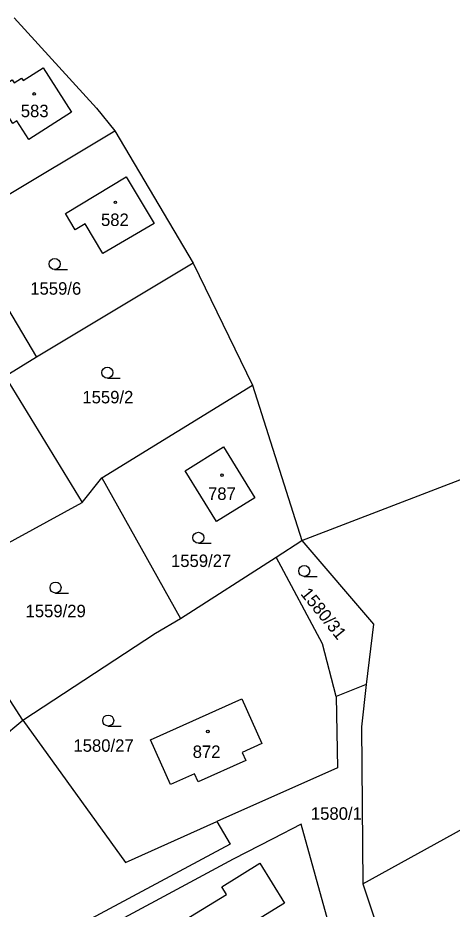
# Model space of a CAD drawing. Extents: x -725728 to -720881, y -1068679 to -1063504.
# Drawn here: x -723628.2 to -723569, y -1066824.1 to -1066702.5 of the extents above; entities that cross this region are included whole.
import ezdxf

# ---------------------------------------------------------------- set-up
doc = ezdxf.new("R2010")
doc.units = 0
for name, color, linetype in [('Hranice parcel', 7, 'Continuous'), ('Parcelní čísla', 7, 'Continuous'), ('Značky budov', 7, 'Continuous'), ('Značky kultur', 7, 'Continuous')]:
    doc.layers.add(name, color=color, linetype=linetype)

# ---------------------------------------------------------------- blocks, each defined once
blk = doc.blocks.new('4.02_3')
at = {"layer": 'Značky budov'}
blk.add_circle((-0.001, 0), 0.0175, dxfattribs=at)
blk = doc.blocks.new('4.02_4')
at = {"layer": 'Značky budov'}
blk.add_circle((-0.001, 0), 0.0175, dxfattribs=at)
blk = doc.blocks.new('3.04_3')
at = {"layer": 'Značky kultur'}
blk.add_line((0.001, 0), (0.176, 0), dxfattribs=at)
blk.add_circle((0.001, 0.075), 0.075, dxfattribs=at)
blk = doc.blocks.new('3.04_2')
at = {"layer": 'Značky kultur'}
blk.add_line((0.001, 0), (0.176, 0), dxfattribs=at)
blk.add_circle((0.001, 0.075), 0.075, dxfattribs=at)

msp = doc.modelspace()

# ---------------------------------------------------------------- linework, layer by layer
at = {"layer": 'Hranice parcel'}
for p, q in [((-723636.48, -1066730.78), (-723614.98, -1066717.9)), ((-723614.98, -1066717.9), (-723604.29, -1066735.93)), ((-723636.48, -1066730.78), (-723625.65, -1066748.76)), ((-723604.29, -1066735.93), (-723625.65, -1066748.76)), ((-723604.29, -1066735.93), (-723596.21, -1066752.59)), ((-723625.65, -1066748.76), (-723629.93, -1066751.39)), ((-723629.93, -1066751.39), (-723619.44, -1066768.6)), ((-723616.74, -1066765.23), (-723596.21, -1066752.59)), ((-723596.21, -1066752.59), (-723589.47, -1066773.79)), ((-723589.47, -1066773.79), (-723540.58, -1066754.95)), ((-723619.44, -1066768.6), (-723616.74, -1066765.23)), ((-723616.74, -1066765.23), (-723606.03, -1066784.4)), ((-723639.64, -1066779.61), (-723619.44, -1066768.6)), ((-723592.97, -1066776.06), (-723589.47, -1066773.79)), ((-723606.03, -1066784.4), (-723592.97, -1066776.06)), ((-723627.51, -1066798.3), (-723639.64, -1066779.61)), ((-723581.16, -1066820.61), (-723518.57, -1066786.09)), ((-723580.67, -1066793.4), (-723584.79, -1066795.05)), ((-723630.58, -1066800.81), (-723627.51, -1066798.3)), ((-723581.16, -1066820.61), (-723574.85, -1066839.29))]:
    msp.add_line(p, q, dxfattribs=at)
for points in [[(-723628.7, -1066702.49), (-723617.48, -1066714.79), (-723614.98, -1066717.9)], [(-723627.7, -1066710.71), (-723627.49, -1066711.03), (-723624.76, -1066709.29), (-723620.9, -1066715.37), (-723626.71, -1066719.07), (-723628.32, -1066716.54), (-723628.89, -1066716.9), (-723631.6, -1066712.61), (-723628.98, -1066710.95), (-723628.72, -1066711.35), (-723627.7, -1066710.71)], [(-723621.72, -1066729.19), (-723613.41, -1066724.19), (-723609.59, -1066730.54), (-723616.63, -1066734.61), (-723619, -1066730.6), (-723620.37, -1066731.42), (-723621.72, -1066729.19)], [(-723595.87, -1066767.96), (-723601.11, -1066771.2), (-723605.38, -1066764.27), (-723600.16, -1066761.01), (-723595.87, -1066767.96)], [(-723589.47, -1066773.79), (-723579.71, -1066785.19), (-723580.67, -1066793.4)], [(-723584.79, -1066795.05), (-723586.63, -1066787.85), (-723592.97, -1066776.06)], [(-723627.51, -1066798.3), (-723609.42, -1066786.4), (-723606.03, -1066784.4)], [(-723580.67, -1066793.4), (-723581.34, -1066799.17), (-723581.16, -1066820.61)], [(-723604.09, -1066805.59), (-723607.37, -1066807.07), (-723610.12, -1066800.97), (-723597.65, -1066795.36), (-723594.93, -1066801.48), (-723597.6, -1066802.67), (-723597.11, -1066803.76), (-723603.6, -1066806.68), (-723604.09, -1066805.59)], [(-723584.79, -1066795.05), (-723584.62, -1066804.76), (-723601.04, -1066812.1)], [(-723627.51, -1066798.3), (-723613.5, -1066817.7), (-723601.04, -1066812.1)], [(-723601.04, -1066812.1), (-723599.24, -1066815.17), (-723644.24, -1066839.3)], [(-723583.68, -1066833.6), (-723589.55, -1066812.45), (-723593.4, -1066814.44), (-723598.84, -1066817.23), (-723643.41, -1066841.2)], [(-723600.39, -1066820.99), (-723595.19, -1066817.76), (-723591.83, -1066823.23), (-723596.8, -1066826.28), (-723594.64, -1066829.67), (-723597.35, -1066831.4), (-723595.82, -1066834.01), (-723602.43, -1066838.02), (-723608.73, -1066827.54), (-723599.74, -1066822.07), (-723600.39, -1066820.99)]]:
    msp.add_lwpolyline(points, dxfattribs=at)

# ---------------------------------------------------------------- block references
at = {"layer": 'Značky budov', "xscale": 10, "yscale": 10}
for name, p in [('4.02_3', (-723625.97, -1066712.87)), ('4.02_4', (-723614.89, -1066727.65)), ('4.02_3', (-723600.34, -1066764.86)), ('4.02_3', (-723602.27, -1066799.82))]:
    msp.add_blockref(name, p, dxfattribs=at)
at = {"layer": 'Značky kultur', "xscale": 10, "yscale": 10}
for name, p in [('3.04_2', (-723623.19, -1066736.81)), ('3.04_3', (-723616, -1066751.63)), ('3.04_3', (-723603.59, -1066774.15)), ('3.04_3', (-723589.15, -1066778.67)), ('3.04_2', (-723623.07, -1066780.94)), ('3.04_2', (-723615.89, -1066799.08))]:
    msp.add_blockref(name, p, dxfattribs=at)

# ---------------------------------------------------------------- texts
at = {"layer": 'Parcelní čísla'}
for s, p in [('583', (-723627.8, -1066716.04)), ('582', (-723616.86, -1066730.88)), ('1559/6', (-723626.51, -1066740.25)), ('1559/2', (-723619.4, -1066755.07)), ('787', (-723602.26, -1066768.24)), ('1559/27', (-723607.31, -1066777.39)), ('1559/29', (-723627.15, -1066784.24)), ('1580/27', (-723620.62, -1066802.59)), ('872', (-723604.35, -1066803.43)), ('1580/1', (-723588.23, -1066811.86))]:
    msp.add_text(s, height=1.7, dxfattribs=at).set_placement(p)
msp.add_text('1580/31', height=1.7, rotation=309, dxfattribs=at).set_placement((-723589.73, -1066781.07))

doc.saveas('drawing.dxf')
